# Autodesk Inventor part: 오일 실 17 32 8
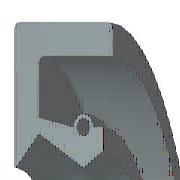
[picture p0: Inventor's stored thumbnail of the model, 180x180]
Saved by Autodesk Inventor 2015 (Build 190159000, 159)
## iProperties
IsCustomPart: 0
Created: 2018-09
Part Number: 오일 실 17 32 8
Material: 고무
Description: 오일-실
Document SubType Name: Modeling
Standard: KS B 2804
Standards Organization: KS
Language: ko-KR
Size Designation: D - 17 32 8
Categories: <MemberInstance><Categories><Category DisplayName="샤프트 부품" InternalName="7f7aeb1f-a693-4053-b835-cee3144e0d98" Mnemonic="SHFT"><Category DisplayName="실링" Intern
Density: 0.93 g/cm^3
Appearance: 고무 - 검은색 - 버전 1.1
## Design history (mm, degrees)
revolve "본체" stored, may be unused: angle "d17" = 90 deg
revolve "스프링1" stored, may be unused: angle "d18" = 90 deg
body "Solid1"
sketch "스케치1"
  geometry: L1 (0, 16)-(8, 16); L2 (8, 14.25)-(1.75, 14.25); L3 (1.75, 10.25)-(4.9, 8.5); L4 (4.9, 8.5)-(0, 8.5); L5 (0, 0)-(9.586, 0) reference; L6 (4.9, 8.5)-(6.3, 9.375); L7 (0, 18)-(0, -3) reference; L8 (-1.941, 0)-(11.507, 0) reference; L9 (4.2, 10.6)-(1.75, 11.21); L10 (1.75, 11.21)-(1.75, 14.25); L11 (0, 16)-(0, 8.588); L12 (4.9, 8.5)-(0, 8.5); L13 (1.75, 10.25)-(0.152, 8.528); L14 (8, 16)-(8, 14.25); L15 (5.6, 10.6)-(6.3, 10.6); L16 (6.3, 10.6)-(6.3, 9.375); C1 r 0.455 at (4.9, 10.6); A1 r 0.7 centre (4.9, 10.6) between (5.6, 10.6) and (4.2, 10.6); A2 r 0.088 centre (0.088, 8.588) between (0, 8.588) and (0.152, 8.528); 1 further point
  constraints: 28 end point, 5 horizontal alignment, 5 point on line, 4 point on circle, 4 vertical alignment, 3 centre point, 3 tangent, 2 collinear, 2 horizontal, 2 perpendicular, 1 coincident, 1 parallel
  dimensions: "d0" = 32 diameter of L1 L5 (= SD2); "d1" = 1.75 distance of L1.end L2.start (= SD); "d2" = 0.91 diameter of C1 (= SPDI); "d3" = 1.4 diameter of A1 (= SPDA); "d4" = 17 diameter of L3.end L5 (= NND); "d5" = 20.5 diameter of L3.start L5 (= TKDM); "d7" = 22.42 diameter of L9.end L5 (= TKDM + 0.24 x SWDT); "d8" = 1.75 distance between parallel lines of L11 L10 (= SD); "d9" = 4.9 distance from line of L11 C1.centre (= SPDST); "d10" = 21.2 diameter of C1.centre L5 (= HLDM); "d11" = 0.0875 radius of A2 (= 0.25 x LAB); "d12" = 6.3 distance between parallel lines of L11 L16 (= SDI); "d13" = 18.75 diameter of L6.end L5 (= ABDM); "d14" = 8 distance from line of L11 L1.end (= SWDT)
fillet "모깎기1" dims "d6" = 0.3 (= RR)
other parameters: "SD2" = 32 [user parameter; used in 1 equation term], "SWDT" = 8 [user parameter; used in 2 equation terms], "RR" = 0.3 [user parameter; used in 1 equation term], "SD" = 1.75 [user parameter; used in 2 equation terms], "NND" = 17 [user parameter; used in 1 equation term], "SPDA" = 1.4 [user parameter; used in 1 equation term], "SPDI" = 0.91 [user parameter; used in 1 equation term], "TKDM" = 20.5 [user parameter; used in 2 equation terms], "HLDM" = 21.2 [user parameter; used in 1 equation term], "ABDM" = 18.75 [user parameter; used in 1 equation term], "SDI" = 6.3 [user parameter; used in 1 equation term], "SPDST" = 4.9 [user parameter; used in 1 equation term], "LAB" = 0.35 [user parameter; used in 1 equation term], "d15" = 0, "d16" = 0, "d19" = 0
